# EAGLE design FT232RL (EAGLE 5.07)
FARNELL: 1696539
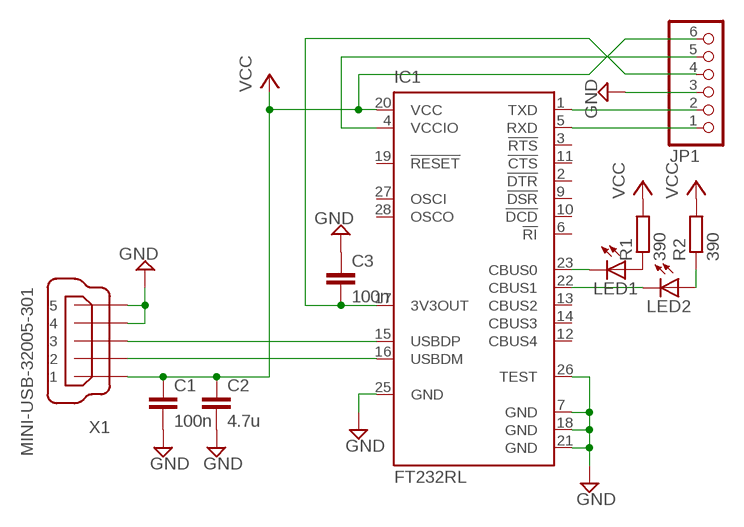
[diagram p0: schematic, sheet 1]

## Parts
C1  100n  C-EUC0603  [C0603]
C2  4.7u  C-EUC0603  [C0603]
C3  100n  C-EUC0603  [C0603]
IC1  FT232RL  [SSOP28]
JP1  PINHD-1X6  [1X06]
LED1  LEDCHIP-LED0805  [CHIP-LED0805]
LED2  LEDCHIP-LED0805  [CHIP-LED0805]
R1  390  R-EU_R0603  [R0603]
R2  390  R-EU_R0603  [R0603]
X1  MINI-USB-32005-301  [32005-301]

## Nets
GND: C1.2 C2.2 C3.1 IC1.7(GND) IC1.18(GND) IC1.21(GND) IC1.25(GND) IC1.26(TEST) JP1.3 X1.4 X1.5
N$1: IC1.16(USBDM) X1.2
N$2: IC1.15(USBDP) X1.3
N$3: LED1.A R1.1
N$5: C3.2 IC1.17(3V3OUT) JP1.4
N$6: IC1.1(TXD) JP1.2
N$7: IC1.5(RXD) JP1.1
N$9: IC1.23(CBUS0) LED1.C
N$10: IC1.22(CBUS1) LED2.C
N$11: LED2.A R2.1
N$12: IC1.4(VCCIO) JP1.5
VCC: C1.1 C2.1 IC1.20(VCC) JP1.6 R1.2 R2.2 X1.1
Unconnected: IC1.2(!DTR) IC1.3(!RTS) IC1.6(!RI) IC1.9(!DSR) IC1.10(!DCD) IC1.11(!CTS) IC1.12(CBUS4) IC1.13(CBUS2) IC1.14(CBUS3) IC1.19(!RESET) IC1.27(OSCI) IC1.28(OSCO)

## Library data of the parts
C1-C3 = rcl:C-EU: CAPACITOR, European symbol
IC1 = ftdichip:FT232R: Source: http://www.ftdichip.com/Documents/DataSheets/DS_FT232R_v104.pdf
JP1 = pinhead:PINHD-1X6: PIN HEADER
LED1 LED2 = led:LED: LED
R1 R2 = rcl:R-EU_: RESISTOR, European symbol
X1 = con-cypressindustries:MINI-USB-: MINI USB-B Conector Source: www.cypressindustries.com

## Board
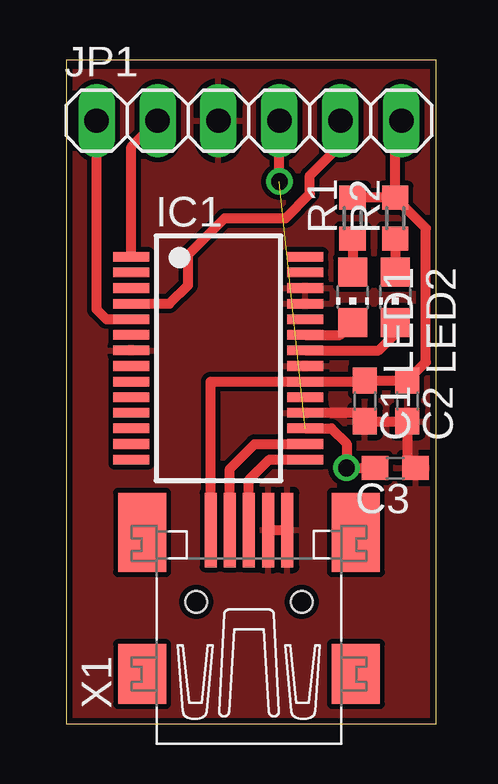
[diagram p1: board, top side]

Size 15.42 x 27.68 mm. Coordinates in mm from the lower left corner, seen from the top.
Outline: 0,0 15.42,0 15.42,27.68 0,27.68 0,0
Copper layers (1*16): Top 0.035mm / dielectric 1.5mm / Bottom 0.035mm
Design rules "default *": minimum track width 10mil, minimum drill 24mil, track to track 8mil, track to pad 8mil, pad to pad 8mil, via to via 8mil, smd to smd 8mil, copper to edge 10mil, drill to drill 8mil, minimum pad ring 10mil, minimum via ring 8mil, stop-mask expansion 4mil, vias tented up to drill 0mil, thermal gap 10mil

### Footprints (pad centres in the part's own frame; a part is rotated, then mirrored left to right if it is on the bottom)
C0603 = smd 1.1 x 1: 1 -0.85,0; 2 0.85,0
SSOP28 = smd 0.4 x 1.5: 1 -4.225,-3.625; 2 -3.575,-3.625; 3 -2.925,-3.625; 4 -2.275,-3.625; 5 -1.625,-3.625; 6 -0.975,-3.625; 7 -0.325,-3.625; 8 0.325,-3.625; 9 0.975,-3.625; 10 1.625,-3.625; 11 2.275,-3.625; 12 2.925,-3.625; 13 3.575,-3.625; 14 4.225,-3.625; 15 4.225,3.625; 16 3.575,3.625; 17 2.925,3.625; 18 2.275,3.625; 19 1.625,3.625; 20 0.975,3.625; 21 0.325,3.625; 22 -0.325,3.625; 23 -0.975,3.625; 24 -1.625,3.625; 25 -2.275,3.625; 26 -2.925,3.625; 27 -3.575,3.625; 28 -4.225,3.625
1X06 = drill 1.016 long: 1 -6.35,0; 2 -3.81,0; 3 -1.27,0; 4 1.27,0; 5 3.81,0; 6 6.35,0
CHIP-LED0805 = smd 1.2 x 1.2: A 0,-1.05; C 0,1.05
R0603 = smd 1 x 1.1: 1 -0.85,0; 2 0.85,0
32005-301 = smd 3.1 x 0.5: 1 3,1.6; 2 3,0.8; 3 3,0; 4 3,-0.8; 5 3,-1.6 | smd 2.5 x 2: M1 -3,-4.45; M2 -3,4.45 | smd 3.3 x 2: M3 2.9,4.45; M4 2.9,-4.45 | hole 0.9: 0,2.2; 0,-2.2

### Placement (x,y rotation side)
C1  12.45,13.46 270 top
C2  14.22,13.46 270 top
C3  13.72,10.67 180 top
IC1  6.35,15.24 270 top
JP1  7.62,25.15 0 top
LED1  11.94,17.78 180 top
LED2  13.72,17.78 180 top
R1  11.94,21.08 90 top
R2  13.72,21.08 90 top
X1  7.62,5.08 90 top

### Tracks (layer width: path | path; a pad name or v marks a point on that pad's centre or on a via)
GND
  Top 0.406: C3.1 14.22,11.09 C2.2 C1.2 12.09,12.96 IC1.18 | X1.4 X1.5
  pour Top: 0,0 0,27.18 15.24,27.18 15.24,0
N$1
  Top 0.406: X1.2 6.82,10.63 7.86,11.66 IC1.16
N$2
  Top 0.406: X1.3 7.62,10.16 8.47,11.02 IC1.15
N$3
  Top 0.406: R1.1 LED1.A
N$5  (via drill 0.7)  (1 unrouted)
  Top 0.406: C3.2 v11.68,10.67 11.68,11.68 11.05,12.31 IC1.17 | v8.89,22.61 JP1.4
N$6
  Top 0.406: JP1.2 2.73,24.06 IC1.1
N$7
  Top 0.406: JP1.1 1.27,17.27 1.68,16.86 IC1.5
N$9
  Top 0.406: IC1.23 11.42,16.21 LED1.C
N$10
  Top 0.406: IC1.22 13.03,15.56 13.72,16.26 LED2.C
N$11
  Top 0.406: R2.1 LED2.A
N$12
  Top 0.406: JP1.5 11.43,24.13 10.16,22.86 10.16,22.1 9.14,21.08 6.6,21.08 5.08,19.56 5.08,18.29 4.31,17.52 IC1.4
VCC
  Top 0.406: R2.2 R1.2 11.77,21.93 | X1.1 6.02,14.27 IC1.20 12.4,14.27 C1.1 C2.1 14.99,15.07 14.99,20.66 R2.2 | JP1.6 13.72,24.89 R2.2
